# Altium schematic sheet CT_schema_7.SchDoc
size 372 x 336 mm
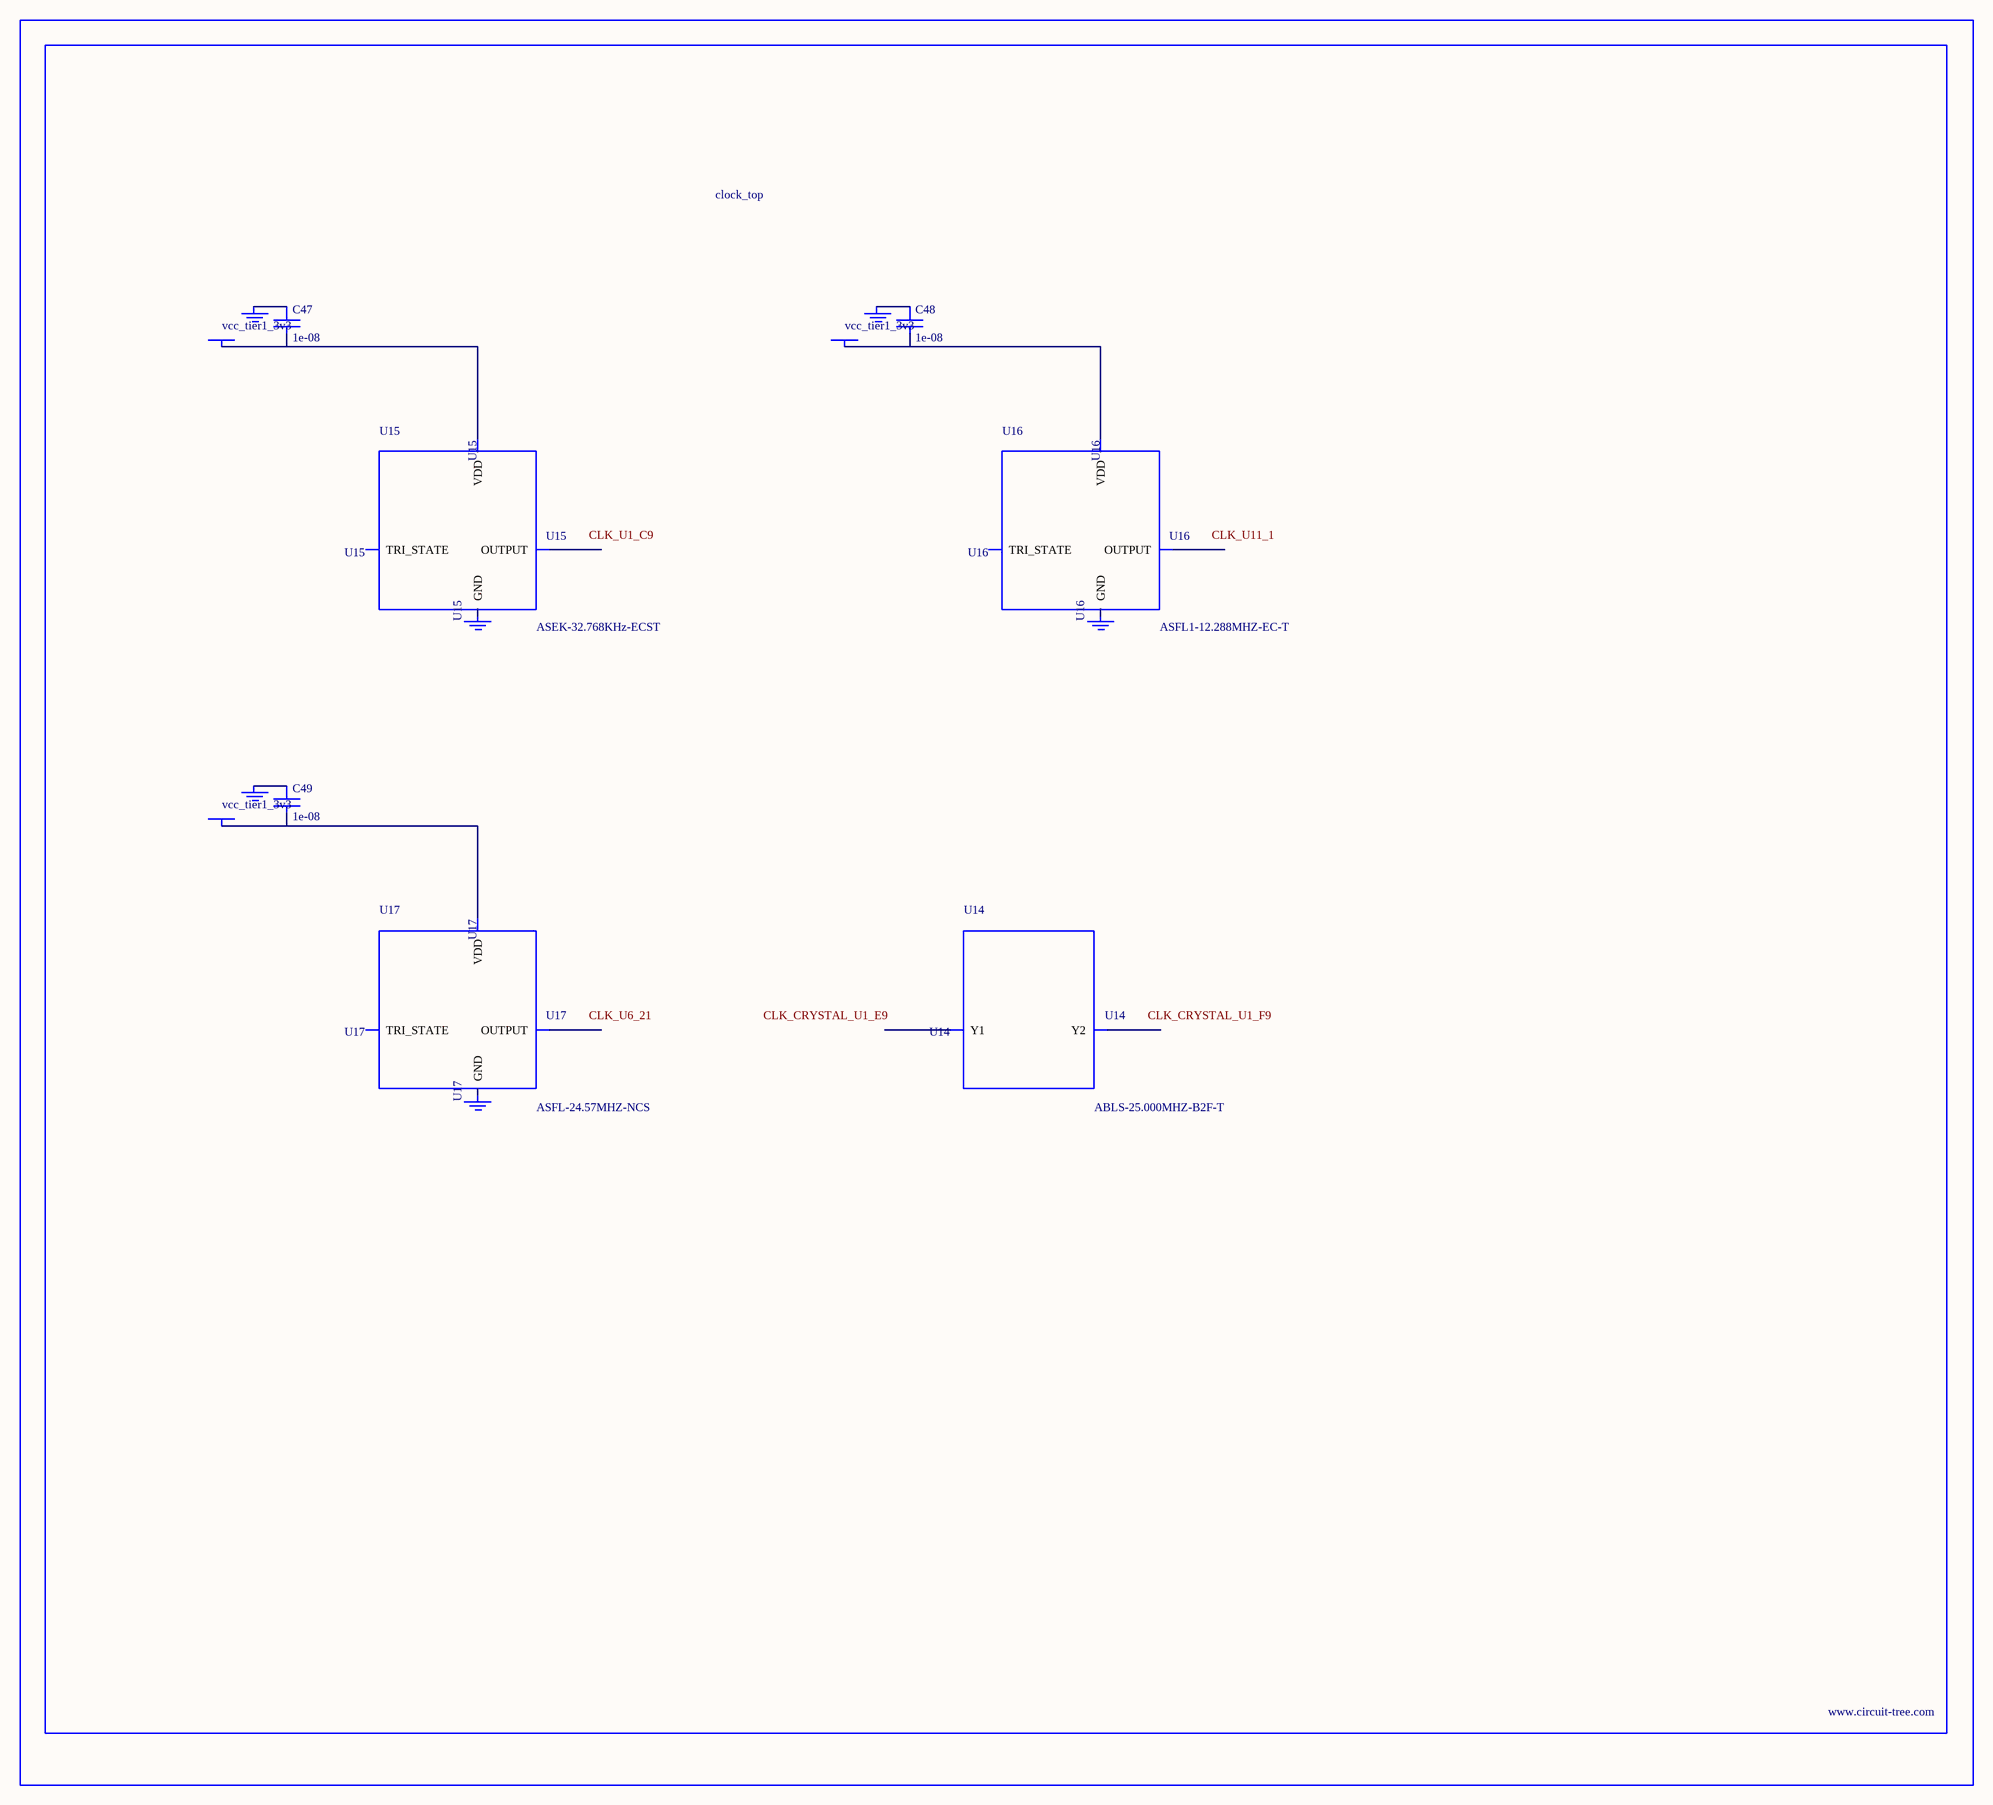
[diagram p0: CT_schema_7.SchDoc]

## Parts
BORDER6  (no value)
C47  1e-08  [C0402]
C48  1e-08  [C0402]
C49  1e-08  [C0402]
GND_INSTANCE_6_0  (no value)
GND_INSTANCE_6_1  (no value)
GND_INSTANCE_6_2  (no value)
GND_INSTANCE_6_3  (no value)
GND_INSTANCE_6_4  (no value)
GND_INSTANCE_6_5  (no value)
POWER_INSTANCE_6_0  vcc_tier1_3v3
POWER_INSTANCE_6_1  vcc_tier1_3v3
POWER_INSTANCE_6_2  vcc_tier1_3v3
U14  ABLS-25.000MHZ-B2F-T  [ABLS-25.000MHZ-B2F-T]
U15  ASEK-32.768KHz-ECST  [ASEK]
U16  ASFL1-12.288MHZ-EC-T  [ASFL1]
U17  ASFL-24.57MHZ-NCS  [ASFL1]

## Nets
NetC47_1: C47.1 GND_INSTANCE_6_0.0(GND)
NetC47_2: C47.2 POWER_INSTANCE_6_0.0(PWR) U15.4(VDD)
NetC48_1: C48.1 GND_INSTANCE_6_2.0(GND)
NetC48_2: C48.2 POWER_INSTANCE_6_1.0(PWR) U16.4(VDD)
NetC49_1: C49.1 GND_INSTANCE_6_4.0(GND)
NetC49_2: C49.2 POWER_INSTANCE_6_2.0(PWR) U17.4(VDD)

Not connected (* = marked no-connect by the designer): GND_INSTANCE_6_1 0(GND); GND_INSTANCE_6_3 0(GND); GND_INSTANCE_6_5 0(GND); U14 1(Y1) 2(Y2); U15 1(TRI_STATE) 2(GND) 3(OUTPUT); U16 1(TRI_STATE) 2(GND) 3(OUTPUT); U17 1(TRI_STATE) 2(GND) 3(OUTPUT)

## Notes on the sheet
- Labels drawn without touching a wire or pin: CLK_CRYSTAL_U1_E9, CLK_CRYSTAL_U1_F9, CLK_U1_C9, CLK_U6_21, CLK_U11_1

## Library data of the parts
BORDER6 = BORDER_PAGE6
C47-C49 = C0402C103K3RAC
GND_INSTANCE_6_0-GND_INSTANCE_6_5 = GND
POWER_INSTANCE_6_0-POWER_INSTANCE_6_2 = PWR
